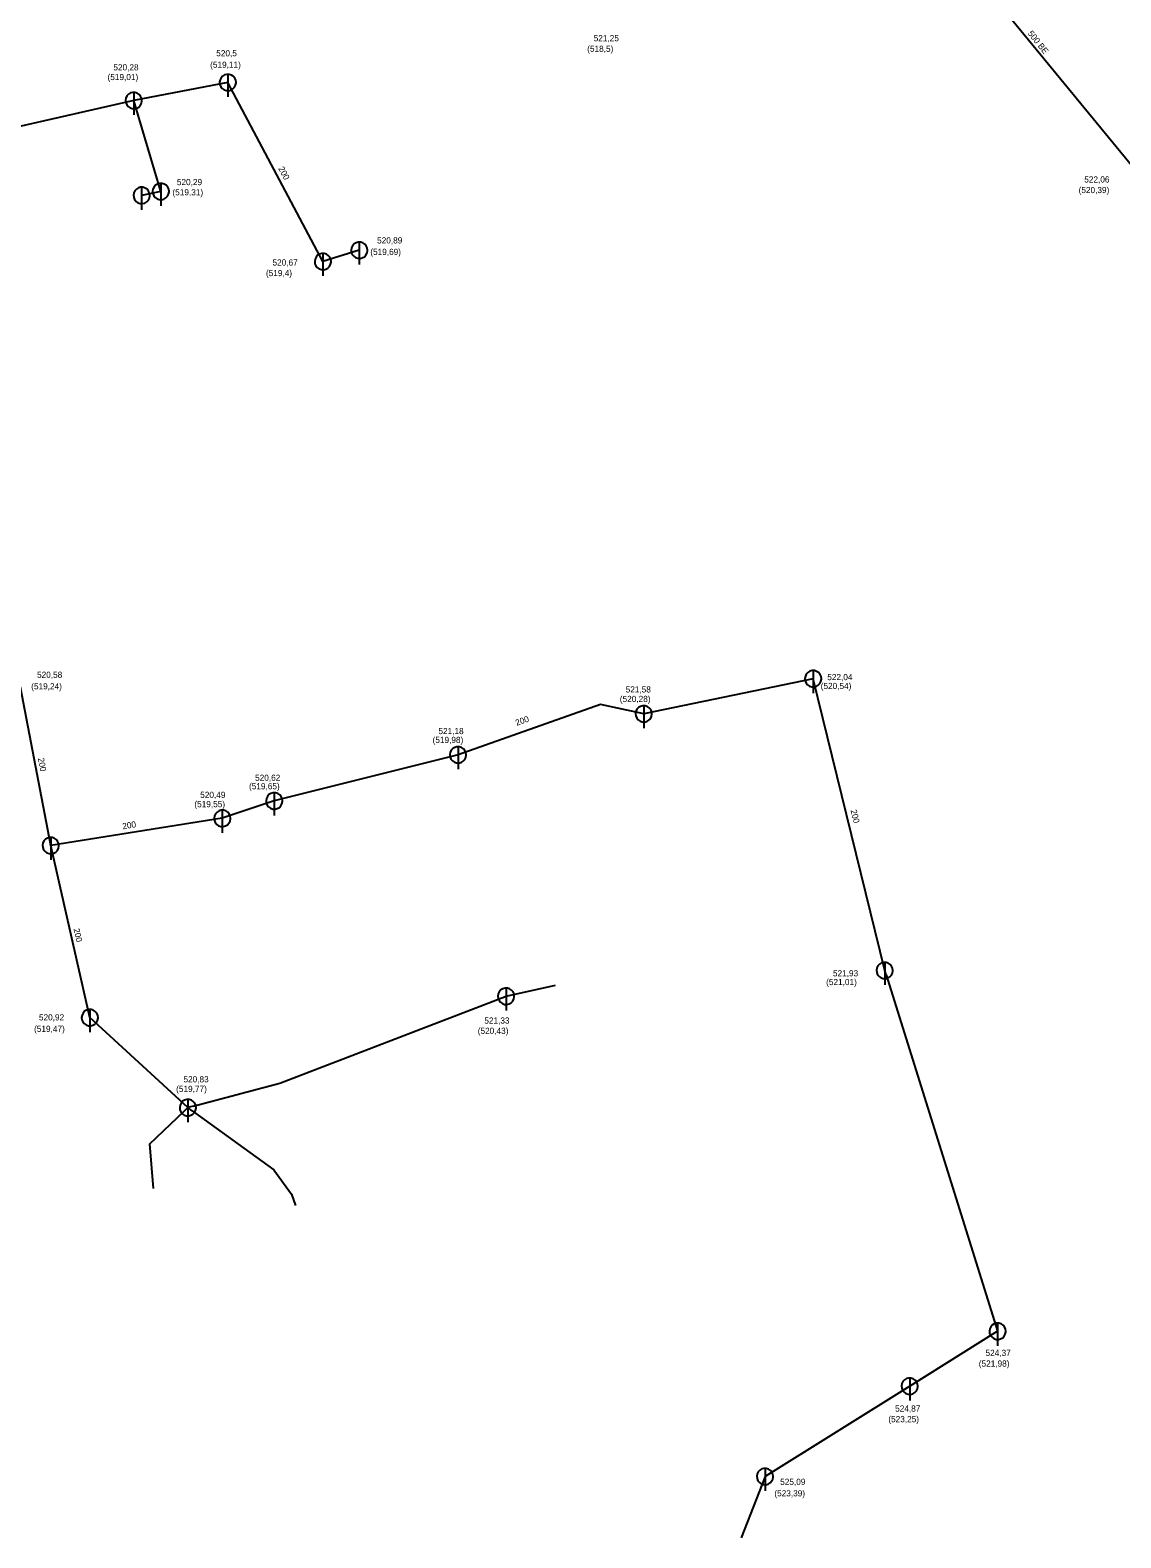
# Model space of a CAD drawing. Extents: x -476058 to -471893, y -1155786 to -1152000.
# Drawn here: x -473765.3 to -473632.5, y -1154111.4 to -1153927.9 of the extents above; entities that cross this region are included whole.
import ezdxf

# ---------------------------------------------------------------- set-up
doc = ezdxf.new("R2010")
doc.units = 0
for name, color, linetype in [('Vrstva 10', 7, 'Continuous'), ('Vrstva 18', 7, 'Continuous'), ('Vrstva 3', 7, 'Continuous'), ('Vrstva 4', 7, 'Continuous'), ('Vrstva 45', 7, 'Continuous'), ('Vrstva 50', 7, 'Continuous'), ('Vrstva 51', 7, 'Continuous')]:
    doc.layers.add(name, color=color, linetype=linetype)

msp = doc.modelspace()

# ---------------------------------------------------------------- linework, layer by layer
at = {"layer": 'Vrstva 10'}
for p, q in [((-473741.22, -1153933.23), (-473741.22, -1153935.98)), ((-473752.67, -1153935.43), (-473752.67, -1153938.18)), ((-473751.71, -1153946.98), (-473751.71, -1153949.73)), ((-473749.38, -1153946.5), (-473749.38, -1153949.25)), ((-473725.22, -1153953.66), (-473725.22, -1153956.41)), ((-473729.65, -1153955.04), (-473729.65, -1153957.79)), ((-473669.98, -1154005.83), (-473669.98, -1154008.58)), ((-473690.6, -1154010.1), (-473690.6, -1154012.85)), ((-473713.2, -1154015.1), (-473713.2, -1154017.84)), ((-473735.57, -1154020.71), (-473735.57, -1154023.46)), ((-473741.89, -1154022.82), (-473741.89, -1154025.57)), ((-473762.78, -1154026.14), (-473762.78, -1154028.89)), ((-473661.27, -1154041.35), (-473661.27, -1154044.1)), ((-473707.35, -1154044.49), (-473707.35, -1154047.24)), ((-473758.01, -1154047.09), (-473758.01, -1154049.84)), ((-473746.08, -1154058.05), (-473746.08, -1154060.8)), ((-473647.53, -1154085.28), (-473647.53, -1154088.03)), ((-473658.23, -1154091.96), (-473658.23, -1154094.71)), ((-473675.84, -1154102.96), (-473675.84, -1154105.71))]:
    msp.add_line(p, q, dxfattribs=at)
for points in [[(-473740.22, -1153934.23), (-473740.26, -1153933.95), (-473740.38, -1153933.69), (-473740.56, -1153933.48), (-473740.79, -1153933.32), (-473741.07, -1153933.24), (-473741.35, -1153933.24), (-473741.62, -1153933.31), (-473741.86, -1153933.46), (-473742.05, -1153933.67), (-473742.17, -1153933.92), (-473742.22, -1153934.2), (-473742.19, -1153934.48), (-473742.08, -1153934.74), (-473741.9, -1153934.96), (-473741.67, -1153935.12), (-473741.4, -1153935.21), (-473741.12, -1153935.23), (-473740.85, -1153935.16), (-473740.6, -1153935.02), (-473740.41, -1153934.81), (-473740.28, -1153934.56), (-473740.22, -1153934.29), (-473740.22, -1153934.23)], [(-473751.67, -1153936.43), (-473751.71, -1153936.15), (-473751.83, -1153935.89), (-473752.01, -1153935.68), (-473752.24, -1153935.53), (-473752.52, -1153935.44), (-473752.8, -1153935.44), (-473753.07, -1153935.51), (-473753.31, -1153935.66), (-473753.5, -1153935.87), (-473753.62, -1153936.12), (-473753.67, -1153936.4), (-473753.64, -1153936.68), (-473753.53, -1153936.94), (-473753.35, -1153937.16), (-473753.12, -1153937.32), (-473752.85, -1153937.41), (-473752.57, -1153937.43), (-473752.3, -1153937.36), (-473752.05, -1153937.22), (-473751.86, -1153937.01), (-473751.73, -1153936.76), (-473751.67, -1153936.49), (-473751.67, -1153936.43)], [(-473750.71, -1153947.98), (-473750.75, -1153947.7), (-473750.86, -1153947.45), (-473751.05, -1153947.23), (-473751.28, -1153947.08), (-473751.55, -1153946.99), (-473751.83, -1153946.99), (-473752.11, -1153947.06), (-473752.35, -1153947.21), (-473752.54, -1153947.42), (-473752.66, -1153947.68), (-473752.71, -1153947.95), (-473752.67, -1153948.23), (-473752.57, -1153948.49), (-473752.39, -1153948.71), (-473752.16, -1153948.88), (-473751.89, -1153948.97), (-473751.61, -1153948.98), (-473751.33, -1153948.91), (-473751.09, -1153948.77), (-473750.89, -1153948.56), (-473750.76, -1153948.31), (-473750.71, -1153948.04), (-473750.71, -1153947.98)], [(-473748.38, -1153947.5), (-473748.41, -1153947.23), (-473748.53, -1153946.97), (-473748.71, -1153946.75), (-473748.95, -1153946.6), (-473749.22, -1153946.52), (-473749.5, -1153946.51), (-473749.77, -1153946.59), (-473750.01, -1153946.74), (-473750.2, -1153946.94), (-473750.33, -1153947.2), (-473750.38, -1153947.48), (-473750.34, -1153947.76), (-473750.23, -1153948.02), (-473750.06, -1153948.24), (-473749.83, -1153948.4), (-473749.56, -1153948.49), (-473749.28, -1153948.5), (-473749, -1153948.43), (-473748.76, -1153948.29), (-473748.56, -1153948.09), (-473748.43, -1153947.84), (-473748.38, -1153947.56), (-473748.38, -1153947.5)], [(-473724.22, -1153954.66), (-473724.26, -1153954.38), (-473724.38, -1153954.12), (-473724.56, -1153953.91), (-473724.79, -1153953.76), (-473725.07, -1153953.67), (-473725.35, -1153953.67), (-473725.62, -1153953.74), (-473725.86, -1153953.89), (-473726.05, -1153954.1), (-473726.17, -1153954.35), (-473726.22, -1153954.63), (-473726.19, -1153954.91), (-473726.08, -1153955.17), (-473725.9, -1153955.39), (-473725.67, -1153955.55), (-473725.4, -1153955.64), (-473725.12, -1153955.66), (-473724.85, -1153955.59), (-473724.6, -1153955.45), (-473724.41, -1153955.24), (-473724.28, -1153954.99), (-473724.22, -1153954.72), (-473724.22, -1153954.66)], [(-473728.65, -1153956.04), (-473728.69, -1153955.76), (-473728.81, -1153955.5), (-473728.99, -1153955.29), (-473729.23, -1153955.14), (-473729.49, -1153955.05), (-473729.78, -1153955.05), (-473730.05, -1153955.12), (-473730.29, -1153955.27), (-473730.48, -1153955.48), (-473730.6, -1153955.73), (-473730.65, -1153956.01), (-473730.62, -1153956.29), (-473730.51, -1153956.55), (-473730.33, -1153956.77), (-473730.1, -1153956.93), (-473729.83, -1153957.02), (-473729.55, -1153957.04), (-473729.28, -1153956.97), (-473729.03, -1153956.83), (-473728.84, -1153956.62), (-473728.71, -1153956.37), (-473728.65, -1153956.1), (-473728.65, -1153956.04)], [(-473668.98, -1154006.83), (-473669.02, -1154006.55), (-473669.14, -1154006.3), (-473669.32, -1154006.08), (-473669.56, -1154005.93), (-473669.83, -1154005.84), (-473670.11, -1154005.84), (-473670.38, -1154005.92), (-473670.62, -1154006.06), (-473670.81, -1154006.27), (-473670.93, -1154006.53), (-473670.98, -1154006.8), (-473670.95, -1154007.09), (-473670.84, -1154007.35), (-473670.66, -1154007.56), (-473670.43, -1154007.73), (-473670.16, -1154007.82), (-473669.88, -1154007.83), (-473669.61, -1154007.76), (-473669.36, -1154007.62), (-473669.17, -1154007.42), (-473669.04, -1154007.17), (-473668.98, -1154006.89), (-473668.98, -1154006.83)], [(-473689.6, -1154011.1), (-473689.63, -1154010.83), (-473689.75, -1154010.57), (-473689.93, -1154010.35), (-473690.17, -1154010.2), (-473690.44, -1154010.12), (-473690.72, -1154010.11), (-473690.99, -1154010.19), (-473691.23, -1154010.34), (-473691.42, -1154010.54), (-473691.55, -1154010.8), (-473691.6, -1154011.08), (-473691.56, -1154011.36), (-473691.45, -1154011.62), (-473691.28, -1154011.84), (-473691.04, -1154012), (-473690.78, -1154012.09), (-473690.49, -1154012.1), (-473690.22, -1154012.03), (-473689.98, -1154011.89), (-473689.78, -1154011.69), (-473689.65, -1154011.44), (-473689.6, -1154011.16), (-473689.6, -1154011.1)], [(-473712.2, -1154016.1), (-473712.24, -1154015.82), (-473712.36, -1154015.56), (-473712.54, -1154015.35), (-473712.78, -1154015.19), (-473713.05, -1154015.11), (-473713.33, -1154015.1), (-473713.6, -1154015.18), (-473713.84, -1154015.33), (-473714.03, -1154015.54), (-473714.15, -1154015.79), (-473714.2, -1154016.07), (-473714.17, -1154016.35), (-473714.06, -1154016.61), (-473713.88, -1154016.83), (-473713.65, -1154016.99), (-473713.38, -1154017.08), (-473713.1, -1154017.09), (-473712.83, -1154017.03), (-473712.58, -1154016.88), (-473712.39, -1154016.68), (-473712.26, -1154016.43), (-473712.2, -1154016.15), (-473712.2, -1154016.1)], [(-473734.57, -1154021.71), (-473734.61, -1154021.43), (-473734.73, -1154021.17), (-473734.91, -1154020.96), (-473735.15, -1154020.8), (-473735.42, -1154020.72), (-473735.7, -1154020.72), (-473735.97, -1154020.79), (-473736.21, -1154020.94), (-473736.4, -1154021.15), (-473736.52, -1154021.4), (-473736.57, -1154021.68), (-473736.54, -1154021.96), (-473736.43, -1154022.22), (-473736.25, -1154022.44), (-473736.02, -1154022.6), (-473735.75, -1154022.69), (-473735.47, -1154022.71), (-473735.2, -1154022.64), (-473734.95, -1154022.5), (-473734.76, -1154022.29), (-473734.63, -1154022.04), (-473734.57, -1154021.77), (-473734.57, -1154021.71)], [(-473740.89, -1154023.82), (-473740.93, -1154023.55), (-473741.05, -1154023.29), (-473741.23, -1154023.07), (-473741.47, -1154022.92), (-473741.74, -1154022.84), (-473742.02, -1154022.83), (-473742.29, -1154022.91), (-473742.53, -1154023.06), (-473742.72, -1154023.27), (-473742.85, -1154023.52), (-473742.89, -1154023.8), (-473742.86, -1154024.08), (-473742.75, -1154024.34), (-473742.57, -1154024.56), (-473742.34, -1154024.72), (-473742.08, -1154024.81), (-473741.79, -1154024.82), (-473741.52, -1154024.75), (-473741.28, -1154024.61), (-473741.08, -1154024.41), (-473740.95, -1154024.16), (-473740.89, -1154023.88), (-473740.89, -1154023.82)], [(-473761.78, -1154027.14), (-473761.82, -1154026.86), (-473761.94, -1154026.6), (-473762.12, -1154026.39), (-473762.35, -1154026.24), (-473762.62, -1154026.15), (-473762.91, -1154026.15), (-473763.18, -1154026.22), (-473763.42, -1154026.37), (-473763.61, -1154026.58), (-473763.73, -1154026.83), (-473763.78, -1154027.11), (-473763.75, -1154027.39), (-473763.64, -1154027.65), (-473763.46, -1154027.87), (-473763.23, -1154028.03), (-473762.96, -1154028.12), (-473762.68, -1154028.14), (-473762.41, -1154028.07), (-473762.16, -1154027.93), (-473761.97, -1154027.72), (-473761.84, -1154027.47), (-473761.78, -1154027.2), (-473761.78, -1154027.14)], [(-473660.27, -1154042.35), (-473660.31, -1154042.07), (-473660.43, -1154041.81), (-473660.61, -1154041.6), (-473660.85, -1154041.45), (-473661.11, -1154041.36), (-473661.4, -1154041.36), (-473661.67, -1154041.43), (-473661.91, -1154041.58), (-473662.1, -1154041.79), (-473662.22, -1154042.04), (-473662.27, -1154042.32), (-473662.24, -1154042.6), (-473662.13, -1154042.86), (-473661.95, -1154043.08), (-473661.72, -1154043.24), (-473661.45, -1154043.33), (-473661.17, -1154043.35), (-473660.9, -1154043.28), (-473660.65, -1154043.14), (-473660.46, -1154042.93), (-473660.33, -1154042.68), (-473660.27, -1154042.41), (-473660.27, -1154042.35)], [(-473706.35, -1154045.49), (-473706.39, -1154045.21), (-473706.5, -1154044.95), (-473706.69, -1154044.74), (-473706.92, -1154044.58), (-473707.19, -1154044.5), (-473707.47, -1154044.5), (-473707.75, -1154044.57), (-473707.99, -1154044.72), (-473708.18, -1154044.93), (-473708.3, -1154045.18), (-473708.35, -1154045.46), (-473708.32, -1154045.74), (-473708.21, -1154046), (-473708.03, -1154046.22), (-473707.8, -1154046.38), (-473707.53, -1154046.47), (-473707.25, -1154046.48), (-473706.97, -1154046.42), (-473706.73, -1154046.27), (-473706.53, -1154046.07), (-473706.4, -1154045.82), (-473706.35, -1154045.54), (-473706.35, -1154045.49)], [(-473757.01, -1154048.09), (-473757.05, -1154047.81), (-473757.17, -1154047.55), (-473757.35, -1154047.34), (-473757.59, -1154047.19), (-473757.85, -1154047.1), (-473758.14, -1154047.1), (-473758.41, -1154047.17), (-473758.65, -1154047.32), (-473758.84, -1154047.53), (-473758.96, -1154047.78), (-473759.01, -1154048.06), (-473758.98, -1154048.34), (-473758.87, -1154048.6), (-473758.69, -1154048.82), (-473758.46, -1154048.98), (-473758.19, -1154049.07), (-473757.91, -1154049.09), (-473757.64, -1154049.02), (-473757.39, -1154048.88), (-473757.2, -1154048.67), (-473757.07, -1154048.42), (-473757.01, -1154048.15), (-473757.01, -1154048.09)], [(-473745.08, -1154059.05), (-473745.12, -1154058.78), (-473745.24, -1154058.52), (-473745.42, -1154058.3), (-473745.66, -1154058.15), (-473745.93, -1154058.07), (-473746.21, -1154058.06), (-473746.48, -1154058.14), (-473746.72, -1154058.28), (-473746.91, -1154058.49), (-473747.03, -1154058.75), (-473747.08, -1154059.03), (-473747.05, -1154059.31), (-473746.94, -1154059.57), (-473746.76, -1154059.79), (-473746.53, -1154059.95), (-473746.26, -1154060.04), (-473745.98, -1154060.05), (-473745.71, -1154059.98), (-473745.46, -1154059.84), (-473745.27, -1154059.64), (-473745.14, -1154059.39), (-473745.08, -1154059.11), (-473745.08, -1154059.05)], [(-473646.53, -1154086.28), (-473646.57, -1154086), (-473646.69, -1154085.74), (-473646.87, -1154085.53), (-473647.1, -1154085.38), (-473647.38, -1154085.29), (-473647.66, -1154085.29), (-473647.93, -1154085.36), (-473648.17, -1154085.51), (-473648.36, -1154085.72), (-473648.48, -1154085.97), (-473648.53, -1154086.25), (-473648.5, -1154086.53), (-473648.39, -1154086.79), (-473648.21, -1154087.01), (-473647.98, -1154087.17), (-473647.71, -1154087.26), (-473647.43, -1154087.28), (-473647.16, -1154087.21), (-473646.91, -1154087.07), (-473646.72, -1154086.86), (-473646.59, -1154086.61), (-473646.53, -1154086.34), (-473646.53, -1154086.28)], [(-473657.23, -1154092.96), (-473657.27, -1154092.68), (-473657.39, -1154092.42), (-473657.57, -1154092.21), (-473657.8, -1154092.05), (-473658.08, -1154091.97), (-473658.36, -1154091.97), (-473658.63, -1154092.04), (-473658.87, -1154092.19), (-473659.06, -1154092.4), (-473659.18, -1154092.65), (-473659.23, -1154092.93), (-473659.2, -1154093.21), (-473659.09, -1154093.47), (-473658.91, -1154093.69), (-473658.68, -1154093.85), (-473658.41, -1154093.94), (-473658.13, -1154093.96), (-473657.86, -1154093.89), (-473657.61, -1154093.75), (-473657.42, -1154093.54), (-473657.29, -1154093.29), (-473657.23, -1154093.02), (-473657.23, -1154092.96)], [(-473674.84, -1154103.96), (-473674.88, -1154103.68), (-473675, -1154103.42), (-473675.18, -1154103.21), (-473675.42, -1154103.05), (-473675.68, -1154102.97), (-473675.97, -1154102.97), (-473676.24, -1154103.04), (-473676.48, -1154103.19), (-473676.67, -1154103.4), (-473676.79, -1154103.65), (-473676.84, -1154103.93), (-473676.81, -1154104.21), (-473676.7, -1154104.47), (-473676.52, -1154104.69), (-473676.29, -1154104.85), (-473676.02, -1154104.94), (-473675.74, -1154104.96), (-473675.47, -1154104.89), (-473675.22, -1154104.75), (-473675.03, -1154104.54), (-473674.9, -1154104.29), (-473674.84, -1154104.02), (-473674.84, -1154103.96)]]:
    msp.add_lwpolyline(points, dxfattribs=at)
at = {"layer": 'Vrstva 45'}
for p, q in [((-473695.86, -1154009.96), (-473713.2, -1154016.1)), ((-473690.6, -1154011.1), (-473695.86, -1154009.96))]:
    msp.add_line(p, q, dxfattribs=at)
for points in [[(-473630.11, -1153945.73), (-473656.5, -1153913.55)], [(-473741.22, -1153934.23), (-473752.67, -1153936.43)], [(-473729.65, -1153956.04), (-473741.22, -1153934.23)], [(-473752.67, -1153936.43), (-473775.85, -1153941.7)], [(-473725.22, -1153954.66), (-473729.65, -1153956.04)], [(-473669.98, -1154006.83), (-473690.6, -1154011.1)], [(-473661.27, -1154042.35), (-473669.98, -1154006.83)], [(-473762.78, -1154027.14), (-473766.47, -1154007.87)], [(-473713.2, -1154016.1), (-473735.57, -1154021.71)], [(-473735.57, -1154021.71), (-473741.89, -1154023.82)], [(-473741.89, -1154023.82), (-473762.78, -1154027.14)], [(-473758.01, -1154048.09), (-473762.78, -1154027.14)], [(-473746.08, -1154059.05), (-473758.01, -1154048.09)]]:
    msp.add_lwpolyline(points, dxfattribs=at)
at = {"layer": 'Vrstva 50'}
for points in [[(-473749.38, -1153947.5), (-473752.46, -1153937.13), (-473752.67, -1153936.43)], [(-473749.38, -1153947.5), (-473751.71, -1153947.98)], [(-473661.1, -1154042.89), (-473661.27, -1154042.35)], [(-473661.1, -1154042.89), (-473647.53, -1154086.28)], [(-473647.53, -1154086.28), (-473658.23, -1154092.96)], [(-473658.23, -1154092.96), (-473675.84, -1154103.96)]]:
    msp.add_lwpolyline(points, dxfattribs=at)
at = {"layer": 'Vrstva 51'}
for p, q in [((-473734.88, -1154056.07), (-473707.35, -1154045.49)), ((-473745.42, -1154058.88), (-473734.88, -1154056.07))]:
    msp.add_line(p, q, dxfattribs=at)
for points in [[(-473707.35, -1154045.49), (-473701.34, -1154044.12)], [(-473746.53, -1154059.47), (-473746.08, -1154059.05)], [(-473745.42, -1154058.88), (-473746.08, -1154059.05)], [(-473745.56, -1154059.43), (-473746.08, -1154059.05)], [(-473750.26, -1154068.91), (-473750.73, -1154063.44), (-473746.53, -1154059.47)], [(-473745.56, -1154059.43), (-473735.61, -1154066.64), (-473733.49, -1154069.58), (-473732.98, -1154070.95)], [(-473675.84, -1154103.96), (-473678.76, -1154111.43)]]:
    msp.add_lwpolyline(points, dxfattribs=at)

# ---------------------------------------------------------------- texts
at = {"layer": 'Vrstva 18'}
for s, rotation, p in [('500 BE', 308.6635, (-473643.91, -1153928.28)), ('200 ', 297.9455, (-473735.1, -1153944.7)), ('200 ', 19.4824, (-473706.07, -1154012.57)), ('200 ', 280.8403, (-473764.34, -1154016.53)), ('200 ', 9.4811, (-473753.99, -1154025.17)), ('200 ', 283.782, (-473665.43, -1154022.85)), ('200 ', 282.8267, (-473760.01, -1154037.31))]:
    msp.add_text(s, height=0.75, rotation=rotation, dxfattribs=at).set_placement(p)
at = {"layer": 'Vrstva 3'}
for s, p in [('521,25', (-473696.69, -1153929.21)), ('520,5', (-473742.63, -1153931.04)), ('520,28', (-473755.15, -1153932.76)), ('520,29', (-473747.42, -1153946.73)), ('522,06', (-473636.98, -1153946.41)), ('520,89', (-473723.05, -1153953.83)), ('520,67', (-473735.78, -1153956.52)), ('520,58', (-473764.44, -1154006.72)), ('522,04', (-473668.26, -1154007)), ('521,58', (-473692.8, -1154008.5)), ('521,18', (-473715.59, -1154013.57)), ('520,62', (-473737.9, -1154019.25)), ('520,49', (-473744.58, -1154021.34)), ('521,93', (-473667.57, -1154043.06)), ('520,92', (-473764.21, -1154048.43)), ('521,33', (-473710, -1154048.82)), ('520,83', (-473746.62, -1154055.97)), ('524,37', (-473649, -1154089.28)), ('524,87', (-473660, -1154096.06)), ('525,09', (-473673.99, -1154104.98))]:
    msp.add_text(s, height=0.75, dxfattribs=at).set_placement(p)
at = {"layer": 'Vrstva 4'}
for s, p in [('(518,5)', (-473697.48, -1153930.5)), ('(519,11)', (-473743.37, -1153932.44)), ('(519,01)', (-473755.86, -1153933.94)), ('(520,39)', (-473637.67, -1153947.7)), ('(519,31)', (-473747.96, -1153947.97)), ('(519,69)', (-473723.88, -1153955.23)), ('(519,4)', (-473736.58, -1153957.81)), ('(519,24)', (-473765.15, -1154008.12)), ('(520,54)', (-473669.06, -1154008.08)), ('(520,28)', (-473693.51, -1154009.66)), ('(519,98)', (-473716.3, -1154014.65)), ('(519,65)', (-473738.64, -1154020.29)), ('(519,55)', (-473745.29, -1154022.47)), ('(521,01)', (-473668.4, -1154044.13)), ('(519,47)', (-473764.8, -1154049.83)), ('(520,43)', (-473710.8, -1154050.07)), ('(519,77)', (-473747.51, -1154057.14)), ('(521,98)', (-473649.82, -1154090.58)), ('(523,25)', (-473660.83, -1154097.35)), ('(523,39)', (-473674.7, -1154106.38))]:
    msp.add_text(s, height=0.75, dxfattribs=at).set_placement(p)

doc.saveas('drawing.dxf')
